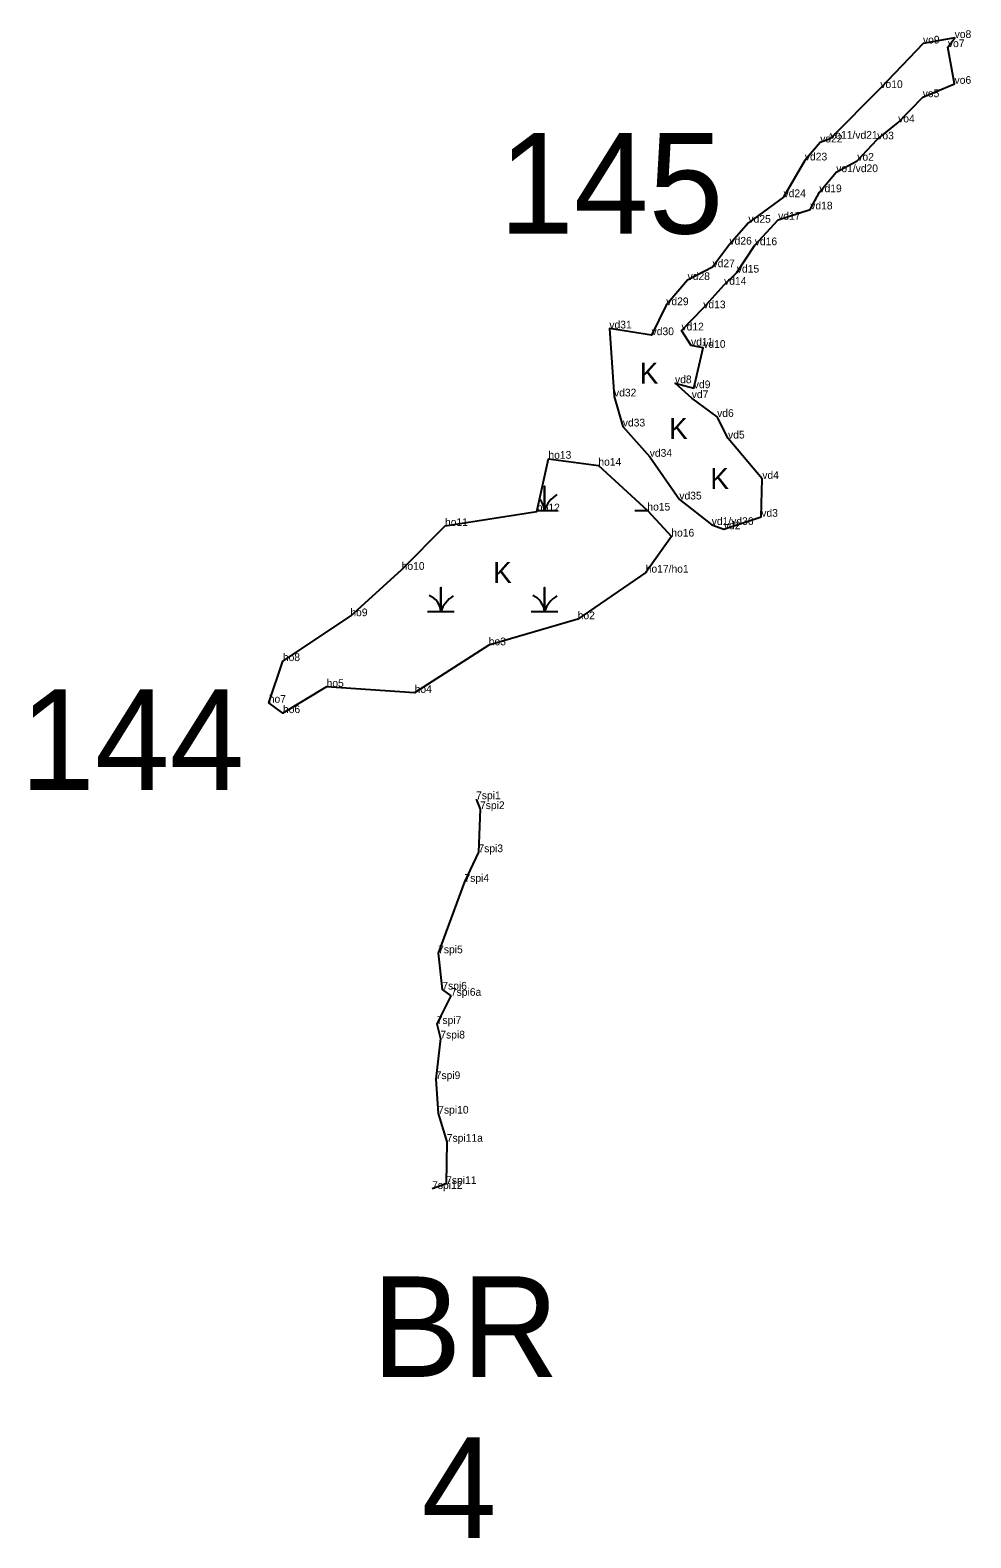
# Model space of a CAD drawing. Extents: x 2072529 to 2268796, y 436423 to 470397.
# Drawn here: x 2167007 to 2167618, y 442281 to 443261 of the extents above; entities that cross this region are included whole.
import ezdxf

# ---------------------------------------------------------------- set-up
doc = ezdxf.new("R2010")
doc.units = 0
for name, color, linetype in [('Default', 7, 'Continuous'), ('Exist Environmental Wetland Boundary', 7, 'Continuous'), ('Exist Environmental Wetland Boundary Cogo Comment', 7, 'Continuous'), ('Exist Environmental Wetland Boundary Cogo Point CELL', 7, 'Continuous'), ('Exist Hydro Jurisdictional Stream or Body of Water NEU Mitigable', 7, 'Continuous'), ('Exist Hydro Jurisdictional Stream or Body of Water NEU Mitigable Cogo Comment', 7, 'Continuous'), ('Exist Hydro Swamp or Marsh', 7, 'Continuous')]:
    doc.layers.add(name, color=color, linetype=linetype)

msp = doc.modelspace()

# ---------------------------------------------------------------- linework, layer by layer
at = {"layer": 'Exist Environmental Wetland Boundary'}
for points in [[(2167449.77, 442939.22), (2167457.64, 442936.43), (2167481.96, 442944.54), (2167482.6, 442969.13), (2167460.36, 442995.39), (2167453.27, 443009.42), (2167436.79, 443021.65), (2167425.93, 443031.31), (2167438.13, 443028.08), (2167444.24, 443054.3), (2167436.31, 443055.74), (2167430.13, 443065.6), (2167444.26, 443080.01), (2167457.77, 443095.27), (2167466.05, 443103.18), (2167477.72, 443120.97), (2167492.9, 443137.56), (2167513.74, 443144.23), (2167519.66, 443155.41), (2167530.59, 443168.45), (2167544.28, 443175.89), (2167557.26, 443189.73), (2167570.81, 443200.77), (2167586.76, 443217.16), (2167607.46, 443225.85), (2167603.12, 443249.68), (2167607.52, 443255.63), (2167586.96, 443252.02), (2167559.28, 443223.09), (2167526.65, 443190.14), (2167520.23, 443187.74), (2167510.24, 443176.06), (2167496.39, 443152.19), (2167473.6, 443135.58), (2167461.27, 443121.36), (2167450.29, 443106.68), (2167434.09, 443098.37), (2167420.24, 443082.01), (2167410.71, 443062.55), (2167383.28, 443066.89), (2167386.3, 443022.72), (2167392.02, 443003.21), (2167409.5, 442983.52), (2167428.73, 442955.77)], [(2167406.89, 442908.26), (2167362.73, 442877.98), (2167304.97, 442861.05), (2167256.83, 442830.1), (2167199.67, 442834.01), (2167171.33, 442816.99), (2167162.12, 442823.71), (2167171.28, 442850.76), (2167215.1, 442879.95), (2167248.39, 442910.07), (2167276.55, 442938.57), (2167336.24, 442948.05), (2167343.71, 442982.23), (2167376.14, 442977.75), (2167407.95, 442948.58), (2167423.53, 442931.69)]]:
    msp.add_lwpolyline(points, close=True, dxfattribs=at)
at = {"layer": 'Exist Environmental Wetland Boundary Cogo Point CELL'}
for p, q in [((2167586.96, 443252.02), (2167586.96, 443252.02)), ((2167603.12, 443249.68), (2167603.12, 443249.68)), ((2167607.52, 443255.63), (2167607.52, 443255.63)), ((2167559.28, 443223.09), (2167559.28, 443223.09)), ((2167586.76, 443217.16), (2167586.76, 443217.16)), ((2167607.46, 443225.85), (2167607.46, 443225.85)), ((2167570.81, 443200.77), (2167570.81, 443200.77)), ((2167520.23, 443187.74), (2167520.23, 443187.74)), ((2167526.65, 443190.14), (2167526.65, 443190.14)), ((2167557.26, 443189.73), (2167557.26, 443189.73)), ((2167510.24, 443176.06), (2167510.24, 443176.06)), ((2167530.59, 443168.45), (2167530.59, 443168.45)), ((2167544.28, 443175.89), (2167544.28, 443175.89)), ((2167496.39, 443152.19), (2167496.39, 443152.19)), ((2167519.66, 443155.41), (2167519.66, 443155.41)), ((2167513.74, 443144.23), (2167513.74, 443144.23)), ((2167473.6, 443135.58), (2167473.6, 443135.58)), ((2167492.9, 443137.56), (2167492.9, 443137.56)), ((2167461.27, 443121.36), (2167461.27, 443121.36)), ((2167477.72, 443120.97), (2167477.72, 443120.97)), ((2167450.29, 443106.68), (2167450.29, 443106.68)), ((2167466.05, 443103.18), (2167466.05, 443103.18)), ((2167434.09, 443098.37), (2167434.09, 443098.37)), ((2167457.77, 443095.27), (2167457.77, 443095.27)), ((2167420.24, 443082.01), (2167420.24, 443082.01)), ((2167444.26, 443080.01), (2167444.26, 443080.01)), ((2167383.28, 443066.89), (2167383.28, 443066.89)), ((2167410.71, 443062.55), (2167410.71, 443062.55)), ((2167430.13, 443065.6), (2167430.13, 443065.6)), ((2167436.31, 443055.74), (2167436.31, 443055.74)), ((2167444.24, 443054.3), (2167444.24, 443054.3)), ((2167425.93, 443031.31), (2167425.93, 443031.31)), ((2167386.3, 443022.72), (2167386.3, 443022.72)), ((2167436.79, 443021.65), (2167436.79, 443021.65)), ((2167438.13, 443028.08), (2167438.13, 443028.08)), ((2167392.02, 443003.21), (2167392.02, 443003.21)), ((2167453.27, 443009.42), (2167453.27, 443009.42)), ((2167460.36, 442995.39), (2167460.36, 442995.39)), ((2167343.71, 442982.23), (2167343.71, 442982.23)), ((2167409.5, 442983.52), (2167409.5, 442983.52)), ((2167376.14, 442977.75), (2167376.14, 442977.75)), ((2167482.6, 442969.13), (2167482.6, 442969.13)), ((2167428.73, 442955.77), (2167428.73, 442955.77)), ((2167336.24, 442948.05), (2167336.24, 442948.05)), ((2167407.95, 442948.58), (2167407.95, 442948.58)), ((2167481.96, 442944.54), (2167481.96, 442944.54)), ((2167276.55, 442938.57), (2167276.55, 442938.57)), ((2167449.77, 442939.22), (2167449.77, 442939.22)), ((2167457.64, 442936.43), (2167457.64, 442936.43)), ((2167423.53, 442931.69), (2167423.53, 442931.69)), ((2167248.39, 442910.07), (2167248.39, 442910.07)), ((2167406.89, 442908.26), (2167406.89, 442908.26)), ((2167215.1, 442879.95), (2167215.1, 442879.95)), ((2167362.73, 442877.98), (2167362.73, 442877.98)), ((2167304.97, 442861.05), (2167304.97, 442861.05)), ((2167171.28, 442850.76), (2167171.28, 442850.76)), ((2167199.67, 442834.01), (2167199.67, 442834.01)), ((2167256.83, 442830.1), (2167256.83, 442830.1)), ((2167162.12, 442823.71), (2167162.12, 442823.71)), ((2167171.33, 442816.99), (2167171.33, 442816.99)), ((2167296.74, 442761.04), (2167296.74, 442761.04)), ((2167299.29, 442754.61), (2167299.29, 442754.61)), ((2167298.28, 442726.61), (2167298.28, 442726.61)), ((2167289.21, 442707.34), (2167289.21, 442707.34)), ((2167272.11, 442660.96), (2167272.11, 442660.96)), ((2167274.81, 442637.32), (2167274.81, 442637.32)), ((2167280.38, 442633.31), (2167280.38, 442633.31)), ((2167271.17, 442615.01), (2167271.17, 442615.01)), ((2167273.52, 442605.57), (2167273.52, 442605.57)), ((2167270.52, 442579.17), (2167270.52, 442579.17)), ((2167272.16, 442556.78), (2167272.16, 442556.78)), ((2167277.72, 442538.47), (2167277.72, 442538.47)), ((2167268.2, 442507.84), (2167268.2, 442507.84)), ((2167277.3, 442511.02), (2167277.3, 442511.02))]:
    msp.add_line(p, q, dxfattribs=at)
at = {"layer": 'Exist Hydro Jurisdictional Stream or Body of Water NEU Mitigable'}
msp.add_lwpolyline([(2167296.74, 442761.04), (2167299.29, 442754.61), (2167298.28, 442726.61), (2167289.21, 442707.34), (2167272.11, 442660.96), (2167274.81, 442637.32), (2167280.38, 442633.31), (2167271.17, 442615.01), (2167273.52, 442605.57), (2167270.52, 442579.17), (2167272.16, 442556.78), (2167277.72, 442538.47), (2167277.3, 442511.02), (2167268.2, 442507.84)], dxfattribs=at)
at = {"layer": 'Exist Hydro Swamp or Marsh'}
for points in [[(2167336.38, 442948.7), (2167341.13, 442948.7), (2167341.13, 442964.48), (2167341.13, 442948.7), (2167349.73, 442948.7)], [(2167399.78, 442948.7), (2167407.81, 442948.7)], [(2167265.28, 442882.9), (2167273.88, 442882.9), (2167273.88, 442898.68), (2167273.88, 442882.9), (2167282.48, 442882.9)], [(2167332.53, 442882.9), (2167341.13, 442882.9), (2167341.13, 442898.68), (2167341.13, 442882.9), (2167349.73, 442882.9)]]:
    msp.add_lwpolyline(points, dxfattribs=at)
for centre, radius, start, end in [((2167328.86, 442947.81), 12.3, 4.14034, 42.11125), ((2167359.37, 442942.64), 19.22, 122.12745, 161.62219), ((2167261.61, 442882.01), 12.3, 4.14034, 67.53497), ((2167328.86, 442882.01), 12.3, 4.14034, 67.53497), ((2167292.12, 442876.84), 19.22, 122.12745, 161.62219), ((2167359.37, 442876.84), 19.22, 122.12745, 161.62219)]:
    msp.add_arc(centre, radius, start, end, dxfattribs=at)

# ---------------------------------------------------------------- texts
at = {"layer": 'Default'}
for s, p in [('145', (2167311.58, 443128.53)), ('144', (2167000.51, 442767.12)), ('BR', (2167229.04, 442385.66)), ('4', (2167261.43, 442281.11))]:
    msp.add_text(s, height=65.34, dxfattribs=at).set_placement(p)
at = {"layer": 'Exist Environmental Wetland Boundary Cogo Comment'}
for s, p in [('vo9', (2167586.96, 443252.02)), ('vo8', (2167607.52, 443255.63)), ('vo7', (2167603.12, 443249.68)), ('vo10', (2167559.28, 443223.09)), ('vo6', (2167607.46, 443225.85)), ('vo5', (2167586.76, 443217.16)), ('vo4', (2167570.81, 443200.77)), ('vd22', (2167520.23, 443187.74)), ('vo11/vd21', (2167526.65, 443190.14)), ('vo3', (2167557.26, 443189.73)), ('vd23', (2167510.24, 443176.06)), ('vo2', (2167544.28, 443175.89)), ('vo1/vd20', (2167530.59, 443168.45)), ('vd19', (2167519.66, 443155.41)), ('vd24', (2167496.39, 443152.19)), ('vd18', (2167513.74, 443144.23)), ('vd25', (2167473.6, 443135.58)), ('vd17', (2167492.9, 443137.56)), ('vd26', (2167461.27, 443121.36)), ('vd16', (2167477.72, 443120.97)), ('vd27', (2167450.29, 443106.68)), ('vd28', (2167434.09, 443098.37)), ('vd14', (2167457.77, 443095.27)), ('vd15', (2167466.05, 443103.18)), ('vd29', (2167420.24, 443082.01)), ('vd13', (2167444.26, 443080.01)), ('vd31', (2167383.28, 443066.89)), ('vd12', (2167430.13, 443065.6)), ('vd30', (2167410.71, 443062.55)), ('vd11', (2167436.31, 443055.74)), ('vd10', (2167444.24, 443054.3)), ('vd8', (2167425.93, 443031.31)), ('vd9', (2167438.13, 443028.08)), ('vd32', (2167386.3, 443022.72)), ('vd7', (2167436.79, 443021.65)), ('vd6', (2167453.27, 443009.42)), ('vd33', (2167392.02, 443003.21)), ('vd5', (2167460.36, 442995.39)), ('ho13', (2167343.71, 442982.23)), ('ho14', (2167376.14, 442977.75)), ('vd34', (2167409.5, 442983.52)), ('vd4', (2167482.6, 442969.13)), ('ho12', (2167336.24, 442948.05)), ('ho15', (2167407.95, 442948.58)), ('vd35', (2167428.73, 442955.77)), ('ho11', (2167276.55, 442938.57)), ('vd1/vd36', (2167449.77, 442939.22)), ('vd3', (2167481.96, 442944.54)), ('ho16', (2167423.53, 442931.69)), ('vd2', (2167457.64, 442936.43)), ('ho10', (2167248.39, 442910.07)), ('ho17/ho1', (2167406.89, 442908.26)), ('ho9', (2167215.1, 442879.95)), ('ho2', (2167362.73, 442877.98)), ('ho3', (2167304.97, 442861.05)), ('ho8', (2167171.28, 442850.76)), ('ho5', (2167199.67, 442834.01)), ('ho4', (2167256.83, 442830.1)), ('ho7', (2167162.12, 442823.71)), ('ho6', (2167171.33, 442816.99))]:
    msp.add_text(s, height=5, dxfattribs=at).set_placement(p)
at = {"layer": 'Exist Hydro Jurisdictional Stream or Body of Water NEU Mitigable Cogo Comment'}
for s, p in [('7spi1', (2167296.74, 442761.04)), ('7spi2', (2167299.29, 442754.61)), ('7spi3', (2167298.28, 442726.61)), ('7spi4', (2167289.21, 442707.34)), ('7spi5', (2167272.11, 442660.96)), ('7spi6', (2167274.81, 442637.32)), ('7spi6a', (2167280.38, 442633.31)), ('7spi7', (2167271.17, 442615.01)), ('7spi8', (2167273.52, 442605.57)), ('7spi9', (2167270.52, 442579.17)), ('7spi10', (2167272.16, 442556.78)), ('7spi11a', (2167277.72, 442538.47)), ('7spi12', (2167268.2, 442507.84)), ('7spi11', (2167277.3, 442511.02))]:
    msp.add_text(s, height=5, dxfattribs=at).set_placement(p)
at = {"layer": 'Exist Hydro Swamp or Marsh'}
for p in [(2167402.96, 443031.08), (2167422, 442995.11), (2167448.79, 442962.68), (2167307.76, 442901.56)]:
    msp.add_text('K', height=13.6, dxfattribs=at).set_placement(p)

doc.saveas('drawing.dxf')
